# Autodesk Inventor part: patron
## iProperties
Created: 2006-04
Part Number: patron
Document SubType Name: Modeling
Designer: Калинин
Author: Калинин
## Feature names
1. Вращение1 [Revolution]
2. Вращение2 [Revolution]
3. Вращение3 [Revolution]
4. Фаска1 [Chamfer]
5. Сопряжение1 [Fillet]
6. Сопряжение2 [Fillet]
7. Сопряжение3 [Fillet]
